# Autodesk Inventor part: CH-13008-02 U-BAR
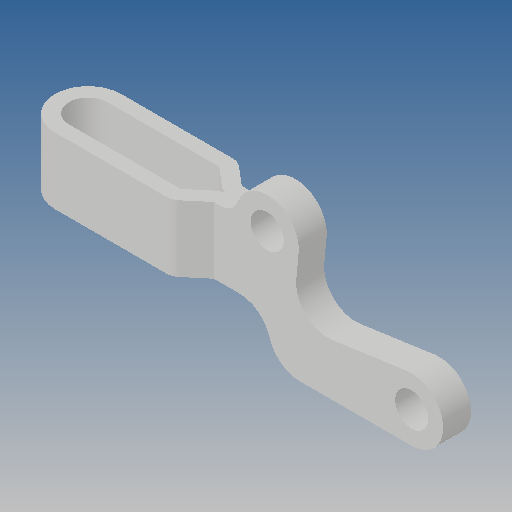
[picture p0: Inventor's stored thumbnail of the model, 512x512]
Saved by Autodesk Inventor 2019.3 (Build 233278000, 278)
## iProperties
Created: 2012-09
Part Number: CH-13008-02 U-BAR
Material: Ogólny
Document SubType Name: Modeling
Designer: CADENGINEERING4
Density: 1 g/cm^3
Appearance: Domyślna
Author: CADENGINEERING4
Revision Number: ÈÎºÎ
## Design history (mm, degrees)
feature "ÇÐ³ý-À­Éì2"
node "Bryła1"
